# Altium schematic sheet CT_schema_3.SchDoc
size 283 x 147 mm
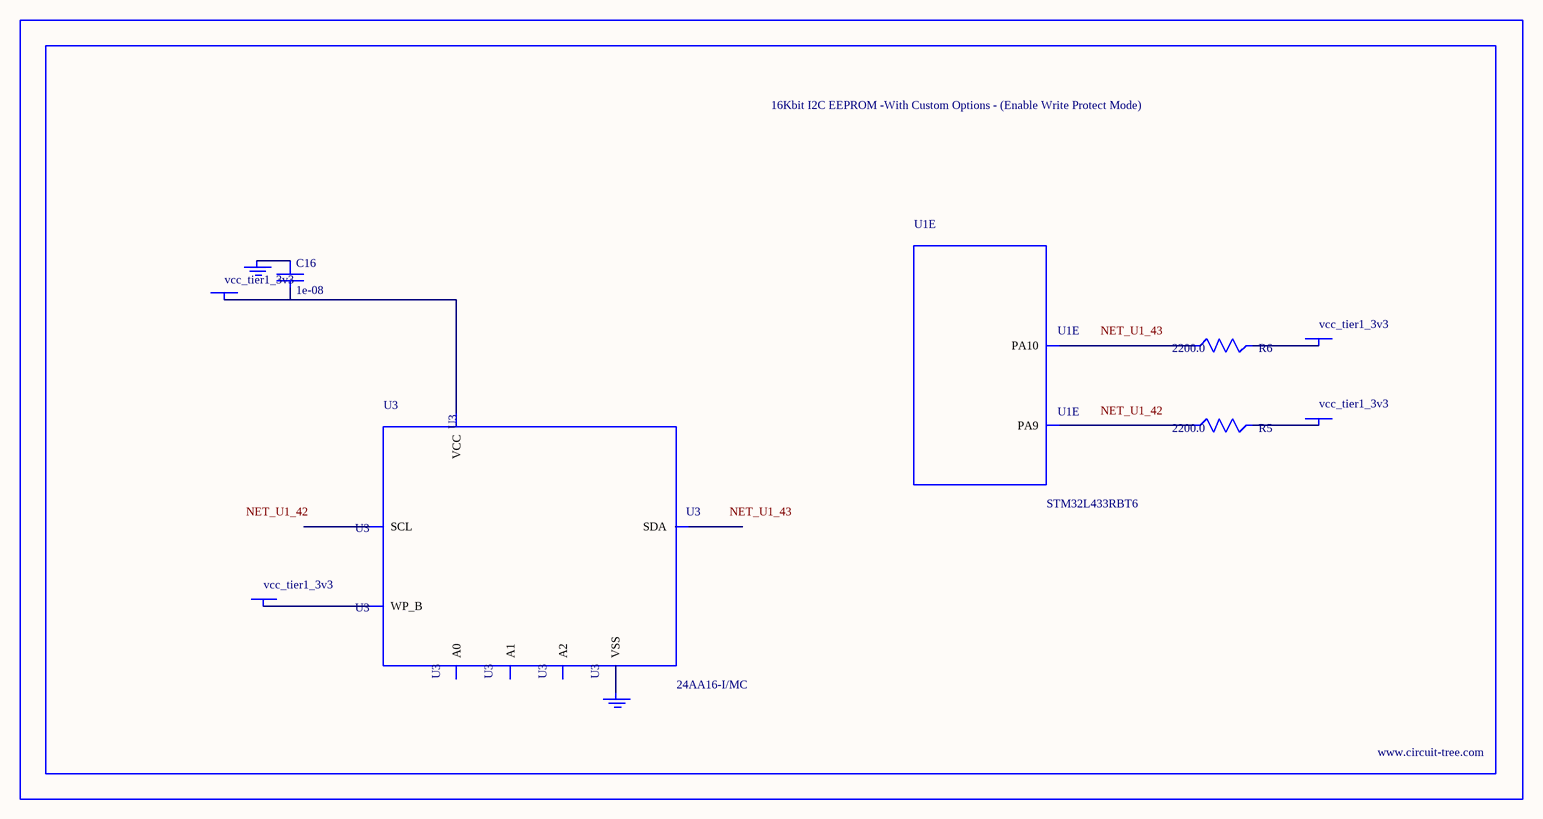
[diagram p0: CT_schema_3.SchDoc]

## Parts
BORDER2  (no value)
C16  1e-08  [C0402]
GND_INSTANCE_2_0  (no value)
GND_INSTANCE_2_1  (no value)
POWER_INSTANCE_2_0  vcc_tier1_3v3
POWER_INSTANCE_2_1  vcc_tier1_3v3
POWER_INSTANCE_2_2  vcc_tier1_3v3
POWER_INSTANCE_2_3  vcc_tier1_3v3
R5  2200.0  [R0603]
R6  2200.0  [R0603]
U1  STM32L433RBT6  [LQFP64]  (part E of 7)
U3  24AA16-I/MC  [TDFN-8/6MM]

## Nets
NetC16_1: C16.1 GND_INSTANCE_2_0.0(GND)
NetC16_2: C16.2 POWER_INSTANCE_2_1.0(PWR) U3.8(VCC)
NetGND_INSTANCE_2_1_0: GND_INSTANCE_2_1.0(GND) U3.4(VSS)
NetPOWER_INSTANCE_2_0_0: POWER_INSTANCE_2_0.0(PWR) U3.7(WP_B)
NetPOWER_INSTANCE_2_2_0: POWER_INSTANCE_2_2.0(PWR) R5.2
NetPOWER_INSTANCE_2_3_0: POWER_INSTANCE_2_3.0(PWR) R6.2
NetR5_1: R5.1 U1.42(PA9)
NetR6_1: R6.1 U1.43(PA10)

Not connected (* = marked no-connect by the designer): U3 1(A0) 2(A1) 3(A2) 5(SDA) 6(SCL)

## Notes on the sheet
- Labels drawn without touching a wire or pin: NET_U1_42, NET_U1_43

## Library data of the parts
BORDER2 = BORDER_PAGE2
C16 = C0402C103K3RAC
GND_INSTANCE_2_0 GND_INSTANCE_2_1 = GND
POWER_INSTANCE_2_0-POWER_INSTANCE_2_3 = PWR
R5 R6 = RC0603JR-072K2L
